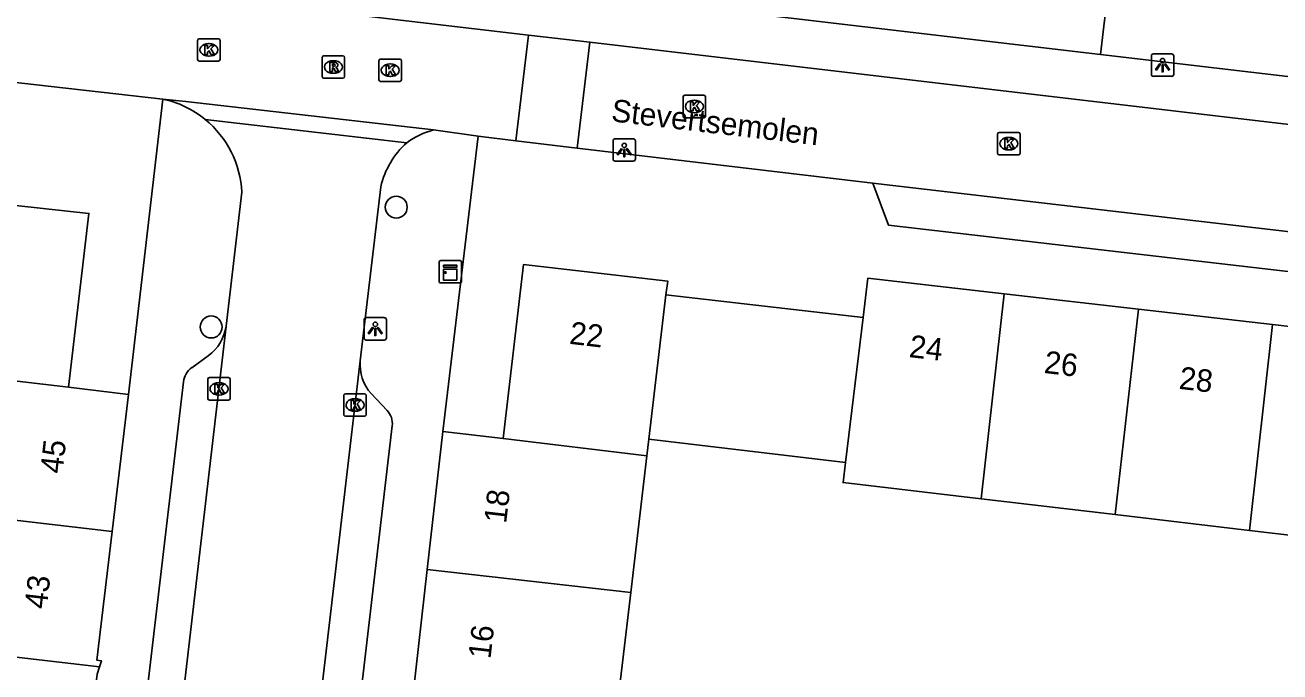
# Model space of a CAD drawing. Extents: x 161243 to 161752, y 384138 to 384885.
# Drawn here: x 161379.5 to 161435.4, y 384400.4 to 384429.2 of the extents above; entities that cross this region are included whole.
import ezdxf

# ---------------------------------------------------------------- set-up
doc = ezdxf.new("R2010")
doc.units = 0
for name, color, linetype in [('IMGEO_Boom', 7, 'Continuous'), ('IMGEO_Groenvoorziening', 7, 'Continuous'), ('IMGEO_Kast', 7, 'Continuous'), ('IMGEO_Kolk', 7, 'Continuous'), ('IMGEO_Lichtpunt', 7, 'Continuous'), ('IMGEO_Openbare_ruimte_label', 7, 'Continuous'), ('IMGEO_Pand', 7, 'Continuous'), ('IMGEO_Pand_nummerreeks', 7, 'Continuous'), ('IMGEO_Parkeervlak_open', 7, 'Continuous'), ('IMGEO_Rijbaan_lokaal_open', 7, 'Continuous'), ('IMGEO_Rioolput', 7, 'Continuous'), ('IMGEO_Voetpad_open', 7, 'Continuous')]:
    doc.layers.add(name, color=color, linetype=linetype)

msp = doc.modelspace()

# ---------------------------------------------------------------- linework, layer by layer
at = {"layer": 'IMGEO_Boom'}
for centre in [(161396.026, 384421.095), (161387.773, 384415.756)]:
    msp.add_circle(centre, 0.489, dxfattribs=at)
at = {"layer": 'IMGEO_Groenvoorziening'}
msp.add_lwpolyline([(161427.439, 384427.904), (161432.833, 384473.658)], dxfattribs=at)
at = {"layer": 'IMGEO_Kast'}
for p, q in [((161397.935, 384417.793), (161397.935, 384418.634)), ((161397.935, 384418.634), (161397.935, 384417.793)), ((161398.01, 384418.718), (161398.851, 384418.718)), ((161398.851, 384418.718), (161398.01, 384418.718)), ((161398.935, 384418.643), (161398.935, 384417.802)), ((161398.935, 384417.802), (161398.935, 384418.643)), ((161398.86, 384417.718), (161398.019, 384417.718)), ((161398.019, 384417.718), (161398.86, 384417.718))]:
    msp.add_line(p, q, dxfattribs=at)
for points in [[(161398.13, 384418.508), (161398.73, 384418.508), (161398.73, 384418.423), (161398.13, 384418.423), (161398.13, 384418.508)], [(161398.13, 384418.333), (161398.73, 384418.333), (161398.73, 384417.844), (161398.13, 384417.844), (161398.13, 384418.333)]]:
    msp.add_lwpolyline(points, dxfattribs=at)
msp.add_circle((161398.214, 384418.182), 0.0377, dxfattribs=at)
for centre, start, end in [((161398.013, 384418.64), 92.4484, 184.2845), ((161398.013, 384418.64), 92.4484, 184.2845), ((161398.857, 384418.64), 2.4484, 94.2845), ((161398.857, 384418.64), 2.4484, 94.2845), ((161398.013, 384417.796), 182.4484, 274.2845), ((161398.013, 384417.796), 182.4484, 274.2845), ((161398.857, 384417.796), 272.4484, 4.2845), ((161398.857, 384417.796), 272.4484, 4.2845)]:
    msp.add_arc(centre, 0.0779, start, end, dxfattribs=at)
at = {"layer": 'IMGEO_Kolk'}
for p, q in [((161387.168, 384427.68), (161387.168, 384428.532)), ((161387.243, 384428.606), (161388.095, 384428.606)), ((161388.169, 384428.532), (161388.169, 384427.68)), ((161387.656, 384428.386), (161387.681, 384428.386)), ((161388.095, 384427.606), (161387.243, 384427.606)), ((161387.679, 384427.826), (161387.654, 384427.826)), ((161395.256, 384426.773), (161395.256, 384427.625)), ((161395.331, 384427.699), (161396.183, 384427.699)), ((161395.744, 384427.479), (161395.769, 384427.479)), ((161396.257, 384427.625), (161396.257, 384426.773)), ((161395.767, 384426.919), (161395.742, 384426.919)), ((161396.183, 384426.699), (161395.331, 384426.699)), ((161408.822, 384425.158), (161408.822, 384426.01)), ((161408.897, 384426.084), (161409.749, 384426.084)), ((161409.31, 384425.864), (161409.335, 384425.864)), ((161409.823, 384426.01), (161409.823, 384425.158)), ((161409.333, 384425.304), (161409.308, 384425.304)), ((161409.749, 384425.084), (161408.897, 384425.084)), ((161422.848, 384423.5), (161422.848, 384424.352)), ((161422.923, 384424.426), (161423.775, 384424.426)), ((161423.336, 384424.206), (161423.361, 384424.206)), ((161423.849, 384424.352), (161423.849, 384423.5)), ((161423.359, 384423.646), (161423.334, 384423.646)), ((161423.775, 384423.426), (161422.923, 384423.426)), ((161387.62, 384412.571), (161387.62, 384413.423)), ((161387.695, 384413.497), (161388.547, 384413.497)), ((161388.621, 384413.423), (161388.621, 384412.571)), ((161388.108, 384413.277), (161388.133, 384413.277)), ((161388.547, 384412.497), (161387.695, 384412.497)), ((161388.131, 384412.717), (161388.106, 384412.717)), ((161393.687, 384411.849), (161393.687, 384412.701)), ((161393.762, 384412.775), (161394.614, 384412.775)), ((161394.175, 384412.555), (161394.2, 384412.555)), ((161394.688, 384412.701), (161394.688, 384411.849)), ((161394.614, 384411.775), (161393.762, 384411.775)), ((161394.198, 384411.995), (161394.173, 384411.995))]:
    msp.add_line(p, q, dxfattribs=at)
for points in [[(161387.168, 384427.68), (161387.168, 384428.532)], [(161387.243, 384428.606), (161388.095, 384428.606)], [(161388.169, 384428.532), (161388.169, 384427.68)], [(161387.489, 384428.306), (161387.612, 384428.306), (161387.612, 384428.155), (161387.742, 384428.306), (161387.906, 384428.306), (161387.76, 384428.155), (161387.913, 384427.906), (161387.761, 384427.906), (161387.676, 384428.07), (161387.612, 384428.003), (161387.612, 384427.906), (161387.489, 384427.906), (161387.489, 384428.306)], [(161388.095, 384427.606), (161387.243, 384427.606)], [(161395.256, 384426.773), (161395.256, 384427.625)], [(161395.331, 384427.699), (161396.183, 384427.699)], [(161395.577, 384427.399), (161395.7, 384427.399), (161395.7, 384427.248), (161395.83, 384427.399), (161395.994, 384427.399), (161395.848, 384427.248), (161396.001, 384426.999), (161395.849, 384426.999), (161395.764, 384427.163), (161395.7, 384427.096), (161395.7, 384426.999), (161395.577, 384426.999), (161395.577, 384427.399)], [(161396.257, 384427.625), (161396.257, 384426.773)], [(161396.183, 384426.699), (161395.331, 384426.699)], [(161408.822, 384425.158), (161408.822, 384426.01)], [(161408.897, 384426.084), (161409.749, 384426.084)], [(161409.143, 384425.784), (161409.266, 384425.784), (161409.266, 384425.633), (161409.396, 384425.784), (161409.56, 384425.784), (161409.414, 384425.633), (161409.567, 384425.384), (161409.415, 384425.384), (161409.33, 384425.548), (161409.266, 384425.481), (161409.266, 384425.384), (161409.143, 384425.384), (161409.143, 384425.784)], [(161409.823, 384426.01), (161409.823, 384425.158)], [(161409.749, 384425.084), (161408.897, 384425.084)], [(161422.848, 384423.5), (161422.848, 384424.352)], [(161422.923, 384424.426), (161423.775, 384424.426)], [(161423.169, 384424.126), (161423.292, 384424.126), (161423.292, 384423.975), (161423.422, 384424.126), (161423.586, 384424.126), (161423.44, 384423.975), (161423.593, 384423.726), (161423.441, 384423.726), (161423.356, 384423.89), (161423.292, 384423.823), (161423.292, 384423.726), (161423.169, 384423.726), (161423.169, 384424.126)], [(161423.849, 384424.352), (161423.849, 384423.5)], [(161423.775, 384423.426), (161422.923, 384423.426)], [(161387.62, 384412.571), (161387.62, 384413.423)], [(161387.695, 384413.497), (161388.547, 384413.497)], [(161388.621, 384413.423), (161388.621, 384412.571)], [(161387.941, 384413.197), (161388.064, 384413.197), (161388.064, 384413.046), (161388.194, 384413.197), (161388.358, 384413.197), (161388.212, 384413.046), (161388.365, 384412.797), (161388.213, 384412.797), (161388.128, 384412.961), (161388.064, 384412.894), (161388.064, 384412.797), (161387.941, 384412.797), (161387.941, 384413.197)], [(161388.547, 384412.497), (161387.695, 384412.497)], [(161393.687, 384411.849), (161393.687, 384412.701)], [(161393.762, 384412.775), (161394.614, 384412.775)], [(161394.008, 384412.475), (161394.131, 384412.475), (161394.131, 384412.324), (161394.261, 384412.475), (161394.425, 384412.475), (161394.279, 384412.324), (161394.432, 384412.075), (161394.28, 384412.075), (161394.195, 384412.239), (161394.131, 384412.172), (161394.131, 384412.075), (161394.008, 384412.075), (161394.008, 384412.475)], [(161394.688, 384412.701), (161394.688, 384411.849)], [(161394.614, 384411.775), (161393.762, 384411.775)]]:
    msp.add_lwpolyline(points, dxfattribs=at)
for centre, start, end in [((161387.245, 384428.53), 91.552, 178.448), ((161387.245, 384428.53), 91.552, 178.448), ((161388.093, 384428.53), 1.552, 88.448), ((161388.093, 384428.53), 1.552, 88.448), ((161387.245, 384427.682), 181.552, 268.448), ((161387.245, 384427.682), 181.552, 268.448), ((161388.093, 384427.682), 271.552, 358.448), ((161388.093, 384427.682), 271.552, 358.448), ((161395.333, 384427.623), 91.552, 178.448), ((161395.333, 384427.623), 91.552, 178.448), ((161396.181, 384427.623), 1.552, 88.448), ((161396.181, 384427.623), 1.552, 88.448), ((161395.333, 384426.775), 181.552, 268.448), ((161395.333, 384426.775), 181.552, 268.448), ((161396.181, 384426.775), 271.552, 358.448), ((161396.181, 384426.775), 271.552, 358.448), ((161408.899, 384426.008), 91.552, 178.448), ((161408.899, 384426.008), 91.552, 178.448), ((161409.747, 384426.008), 1.552, 88.448), ((161409.747, 384426.008), 1.552, 88.448), ((161408.899, 384425.16), 181.552, 268.448), ((161408.899, 384425.16), 181.552, 268.448), ((161409.747, 384425.16), 271.552, 358.448), ((161409.747, 384425.16), 271.552, 358.448), ((161422.925, 384424.35), 91.552, 178.448), ((161422.925, 384424.35), 91.552, 178.448), ((161423.773, 384424.35), 1.552, 88.448), ((161423.773, 384424.35), 1.552, 88.448), ((161422.925, 384423.502), 181.552, 268.448), ((161422.925, 384423.502), 181.552, 268.448), ((161423.773, 384423.502), 271.552, 358.448), ((161423.773, 384423.502), 271.552, 358.448), ((161387.697, 384413.421), 91.552, 178.448), ((161387.697, 384413.421), 91.552, 178.448), ((161388.545, 384413.421), 1.552, 88.448), ((161388.545, 384413.421), 1.552, 88.448), ((161387.697, 384412.573), 181.552, 268.448), ((161387.697, 384412.573), 181.552, 268.448), ((161388.545, 384412.573), 271.552, 358.448), ((161388.545, 384412.573), 271.552, 358.448), ((161393.764, 384412.699), 91.552, 178.448), ((161393.764, 384412.699), 91.552, 178.448), ((161394.612, 384412.699), 1.552, 88.448), ((161394.612, 384412.699), 1.552, 88.448), ((161393.764, 384411.851), 181.552, 268.448), ((161393.764, 384411.851), 181.552, 268.448), ((161394.612, 384411.851), 271.552, 358.448), ((161394.612, 384411.851), 271.552, 358.448)]:
    msp.add_arc(centre, 0.0765, start, end, dxfattribs=at)
for centre, major_axis, ratio, start_param, end_param in [((161387.655, 384428.106), (-0.387, 0.002), 0.722429, 4.712389, 7.853982), ((161387.68, 384428.106), (-0.39, 0.002), 0.717154, 1.570796, 4.712389), ((161395.743, 384427.199), (-0.387, 0.002), 0.722429, 4.712389, 7.853982), ((161395.768, 384427.199), (-0.39, 0.002), 0.717154, 1.570796, 4.712389), ((161409.309, 384425.584), (-0.387, 0.002), 0.722429, 4.712389, 7.853982), ((161409.334, 384425.584), (-0.39, 0.002), 0.717154, 1.570796, 4.712389), ((161423.335, 384423.926), (-0.387, 0.002), 0.722429, 4.712389, 7.853982), ((161423.36, 384423.926), (-0.39, 0.002), 0.717154, 1.570796, 4.712389), ((161388.107, 384412.997), (-0.387, 0.002), 0.722429, 4.712389, 7.853982), ((161388.132, 384412.997), (-0.39, 0.002), 0.717154, 1.570796, 4.712389), ((161394.174, 384412.275), (-0.387, 0.002), 0.722429, 4.712389, 7.853982), ((161394.199, 384412.275), (-0.39, 0.002), 0.717154, 1.570796, 4.712389)]:
    msp.add_ellipse(centre, major_axis=major_axis, ratio=ratio, start_param=start_param, end_param=end_param, dxfattribs=at)
at = {"layer": 'IMGEO_Lichtpunt'}
for p, q in [((161429.706, 384427.829), (161429.706, 384427.022)), ((161429.706, 384427.829), (161429.706, 384427.022)), ((161430.608, 384427.924), (161429.8, 384427.924)), ((161430.608, 384427.924), (161429.8, 384427.924)), ((161430.702, 384427.022), (161430.702, 384427.829)), ((161430.702, 384427.022), (161430.702, 384427.829)), ((161429.8, 384426.928), (161430.608, 384426.928)), ((161429.8, 384426.928), (161430.608, 384426.928)), ((161405.696, 384424.05), (161405.696, 384423.243)), ((161405.696, 384424.05), (161405.696, 384423.243)), ((161406.598, 384424.145), (161405.79, 384424.145)), ((161406.598, 384424.145), (161405.79, 384424.145)), ((161406.692, 384423.243), (161406.692, 384424.05)), ((161406.692, 384423.243), (161406.692, 384424.05)), ((161405.79, 384423.149), (161406.598, 384423.149)), ((161405.79, 384423.149), (161406.598, 384423.149)), ((161394.592, 384416.075), (161394.592, 384415.268)), ((161394.592, 384416.075), (161394.592, 384415.268)), ((161395.494, 384416.17), (161394.686, 384416.17)), ((161395.494, 384416.17), (161394.686, 384416.17)), ((161395.588, 384415.268), (161395.588, 384416.075)), ((161395.588, 384415.268), (161395.588, 384416.075)), ((161394.686, 384415.174), (161395.494, 384415.174)), ((161394.686, 384415.174), (161395.494, 384415.174))]:
    msp.add_line(p, q, dxfattribs=at)
for points in [[(161430.08, 384427.493), (161430.119, 384427.465), (161429.931, 384427.203), (161429.893, 384427.23), (161430.08, 384427.493)], [(161430.182, 384427.445), (161430.229, 384427.445), (161430.229, 384427.123), (161430.182, 384427.123), (161430.182, 384427.445)], [(161430.292, 384427.465), (161430.33, 384427.492), (161430.517, 384427.23), (161430.478, 384427.202), (161430.292, 384427.465)], [(161406.07, 384423.714), (161406.109, 384423.686), (161405.921, 384423.424), (161405.883, 384423.451), (161406.07, 384423.714)], [(161406.172, 384423.666), (161406.219, 384423.666), (161406.219, 384423.344), (161406.172, 384423.344), (161406.172, 384423.666)], [(161406.282, 384423.686), (161406.32, 384423.713), (161406.507, 384423.451), (161406.468, 384423.423), (161406.282, 384423.686)], [(161394.966, 384415.739), (161395.005, 384415.711), (161394.817, 384415.449), (161394.779, 384415.476), (161394.966, 384415.739)], [(161395.068, 384415.691), (161395.115, 384415.691), (161395.115, 384415.369), (161395.068, 384415.369), (161395.068, 384415.691)], [(161395.178, 384415.711), (161395.216, 384415.738), (161395.403, 384415.476), (161395.364, 384415.448), (161395.178, 384415.711)]]:
    msp.add_lwpolyline(points, dxfattribs=at)
for centre in [(161430.205, 384427.627), (161406.195, 384423.848), (161395.091, 384415.873)]:
    msp.add_circle(centre, 0.0994, dxfattribs=at)
for centre, start, end in [((161429.8, 384427.829), 90, 180), ((161429.8, 384427.829), 90, 180), ((161430.608, 384427.829), 0, 90), ((161430.608, 384427.829), 0, 90), ((161429.8, 384427.022), 180, 270), ((161429.8, 384427.022), 180, 270), ((161430.608, 384427.022), 270, 0), ((161430.608, 384427.022), 270, 360), ((161405.79, 384424.05), 90, 180), ((161405.79, 384424.05), 90, 180), ((161406.598, 384424.05), 0, 90), ((161406.598, 384424.05), 0, 90), ((161405.79, 384423.243), 180, 270), ((161405.79, 384423.243), 180, 270), ((161406.598, 384423.243), 270, 0), ((161406.598, 384423.243), 270, 360), ((161394.686, 384416.075), 90, 180), ((161394.686, 384416.075), 90, 180), ((161395.494, 384416.075), 0, 90), ((161395.494, 384416.075), 0, 90), ((161394.686, 384415.268), 180, 270), ((161394.686, 384415.268), 180, 270), ((161395.494, 384415.268), 270, 0), ((161395.494, 384415.268), 270, 360)]:
    msp.add_arc(centre, 0.0946, start, end, dxfattribs=at)
at = {"layer": 'IMGEO_Pand'}
for points in [[(161376.061, 384421.492), (161382.318, 384420.819), (161381.408, 384413.065)], [(161400.801, 384410.777), (161401.706, 384418.545), (161408.14, 384417.794), (161408.057, 384417.189)], [(161416.852, 384416.18), (161417.063, 384417.929), (161423.139, 384417.232)], [(161408.057, 384417.189), (161407.286, 384410.751)], [(161408.057, 384417.189), (161416.852, 384416.18)], [(161422.108, 384408.094), (161423.139, 384417.232)], [(161423.139, 384417.232), (161429.127, 384416.546)], [(161429.127, 384416.546), (161428.094, 384407.392)], [(161429.127, 384416.546), (161435.115, 384415.86)], [(161416.852, 384416.18), (161416.056, 384409.721)], [(161434.08, 384406.689), (161435.115, 384415.86)], [(161435.115, 384415.86), (161441.102, 384415.173)], [(161381.408, 384413.065), (161375.166, 384413.798)], [(161381.408, 384413.065), (161384.082, 384412.738)], [(161384.082, 384412.738), (161383.357, 384406.631)], [(161398.105, 384411.096), (161397.406, 384404.939)], [(161398.105, 384411.096), (161400.801, 384410.777)], [(161407.2, 384410.016), (161400.801, 384410.777)], [(161407.286, 384410.751), (161407.2, 384410.016)], [(161416.056, 384409.721), (161407.286, 384410.751)], [(161407.2, 384410.016), (161406.484, 384403.913)], [(161422.108, 384408.094), (161415.958, 384408.816), (161416.056, 384409.721)], [(161428.094, 384407.392), (161422.108, 384408.094)], [(161374.421, 384407.672), (161383.357, 384406.631)], [(161434.08, 384406.689), (161428.094, 384407.392)], [(161440.066, 384405.987), (161434.08, 384406.689)], [(161383.357, 384406.631), (161382.676, 384400.9), (161382.874, 384400.88), (161382.786, 384400.607)], [(161397.406, 384404.939), (161396.761, 384399.263), (161396.639, 384399.27), (161396.607, 384398.945)], [(161406.484, 384403.913), (161397.406, 384404.939)], [(161406.484, 384403.913), (161405.779, 384397.909)], [(161382.786, 384400.607), (161373.691, 384401.666)], [(161382.786, 384400.607), (161382.68, 384400.278), (161382.051, 384394.962), (161382.312, 384394.905), (161382.283, 384394.576)]]:
    msp.add_lwpolyline(points, dxfattribs=at)
at = {"layer": 'IMGEO_Parkeervlak_open'}
msp.add_lwpolyline([(161459.347, 384417.271), (161457.727, 384415.687), (161417.974, 384420.297), (161417.282, 384422.167)], dxfattribs=at)
at = {"layer": 'IMGEO_Rijbaan_lokaal_open'}
for points in [[(161336.535, 384438.485), (161336.257, 384436.376), (161382.402, 384431.06), (161401.922, 384428.768)], [(161401.363, 384424.054), (161401.922, 384428.768)], [(161401.922, 384428.768), (161404.653, 384428.447)], [(161404.094, 384423.73), (161404.653, 384428.447)], [(161404.653, 384428.447), (161443.686, 384423.864), (161452.639, 384422.825)], [(161385.608, 384425.915), (161367.914, 384427.91)], [(161397.686, 384424.536), (161386.646, 384425.81), (161385.608, 384425.915)], [(161396.501, 384423.968), (161387.504, 384425.007)], [(161397.686, 384424.536), (161399.676, 384424.254)], [(161399.676, 384424.254), (161401.363, 384424.054)], [(161404.094, 384423.73), (161401.363, 384424.054)], [(161417.282, 384422.167), (161404.094, 384423.73)], [(161394.42, 384414.251), (161395.335, 384422.009)], [(161452.092, 384418.115), (161417.282, 384422.167)], [(161389.139, 384421.761), (161388.436, 384415.795)], [(161388.436, 384415.795), (161382.703, 384366.584)], [(161388.778, 384366.166), (161394.42, 384414.251)]]:
    msp.add_lwpolyline(points, dxfattribs=at)
for centre, radius, start, end in [((161384.678, 384421.539), 4.473, 50.8205, 77.9997), ((161384.679, 384421.549), 4.465, 2.7202, 50.7483), ((161398.643, 384421.019), 3.645, 105.2232, 125.9959), ((161399.039, 384421.131), 3.807, 131.8146, 166.6631)]:
    msp.add_arc(centre, radius, start, end, dxfattribs=at)
at = {"layer": 'IMGEO_Rioolput'}
for p, q in [((161392.723, 384426.919), (161392.723, 384427.771)), ((161392.798, 384427.845), (161393.65, 384427.845)), ((161393.211, 384427.625), (161393.236, 384427.625)), ((161393.724, 384427.771), (161393.724, 384426.919)), ((161393.65, 384426.845), (161392.798, 384426.845)), ((161393.234, 384427.065), (161393.209, 384427.065))]:
    msp.add_line(p, q, dxfattribs=at)
for points in [[(161392.723, 384426.919), (161392.723, 384427.771)], [(161392.798, 384427.845), (161393.65, 384427.845)], [(161393.312, 384427.543), (161393.06, 384427.545), (161393.06, 384427.145)], [(161393.238, 384427.464), (161393.184, 384427.464), (161393.184, 384427.383)], [(161393.724, 384427.771), (161393.724, 384426.919)], [(161393.65, 384426.845), (161392.798, 384426.845)], [(161393.06, 384427.145), (161393.184, 384427.145), (161393.184, 384427.307), (161393.195, 384427.307)], [(161393.184, 384427.383), (161393.236, 384427.383)], [(161393.242, 384427.278), (161393.313, 384427.145), (161393.453, 384427.145), (161393.388, 384427.271)]]:
    msp.add_lwpolyline(points, dxfattribs=at)
for centre, radius, start, end in [((161392.8, 384427.769), 0.0765, 91.552, 178.448), ((161392.8, 384427.769), 0.0765, 91.552, 178.448), ((161393.244, 384427.368), 0.0964, 77.0061, 93.1865), ((161393.258, 384427.425), 0.0378, 276.6634, 79.6772), ((161393.311, 384427.433), 0.109, 350.3612, 89.416), ((161393.309, 384427.433), 0.112, 277.5842, 350.9817), ((161393.648, 384427.769), 0.0765, 1.552, 88.448), ((161393.648, 384427.769), 0.0765, 1.552, 88.448), ((161392.8, 384426.921), 0.0765, 181.552, 268.448), ((161392.8, 384426.921), 0.0765, 181.552, 268.448), ((161393.194, 384427.254), 0.0533, 26.0293, 88.6989), ((161393.22, 384427.572), 0.19, 274.7715, 282.9687), ((161393.293, 384427.218), 0.108, 29.5134, 73.7905), ((161393.648, 384426.921), 0.0765, 271.552, 358.448), ((161393.648, 384426.921), 0.0765, 271.552, 358.448)]:
    msp.add_arc(centre, radius, start, end, dxfattribs=at)
for centre, major_axis, ratio, start_param, end_param in [((161393.21, 384427.345), (-0.387, 0.002), 0.722429, 4.712389, 7.853982), ((161393.235, 384427.345), (-0.39, 0.002), 0.717154, 1.570796, 4.712389)]:
    msp.add_ellipse(centre, major_axis=major_axis, ratio=ratio, start_param=start_param, end_param=end_param, dxfattribs=at)
at = {"layer": 'IMGEO_Voetpad_open'}
for points in [[(161410.092, 384429.939), (161427.439, 384427.904)], [(161440.852, 384426.331), (161427.439, 384427.904)], [(161384.082, 384412.738), (161385.608, 384425.915)], [(161399.676, 384424.254), (161398.105, 384411.096)], [(161386.903, 384413.941), (161387.639, 384414.474)], [(161381.37, 384369.393), (161386.534, 384413.313)], [(161395.619, 384412.033), (161394.905, 384412.788)], [(161390.818, 384368.412), (161395.846, 384411.348)]]:
    msp.add_lwpolyline(points, dxfattribs=at)
for centre, radius, start, end in [((161386.485, 384416.071), 1.971, 305.8502, 351.942), ((161396.33, 384414.072), 1.918, 174.6559, 222.0259), ((161387.427, 384413.211), 0.899, 125.6584, 173.4663), ((161394.995, 384411.446), 0.857, 353.426, 43.243)]:
    msp.add_arc(centre, radius, start, end, dxfattribs=at)

# ---------------------------------------------------------------- texts
at = {"layer": 'IMGEO_Openbare_ruimte_label'}
msp.add_text('Stevertsemolen', height=1, rotation=353.337, dxfattribs=at).set_placement((161405.583, 384424.925))
at = {"layer": 'IMGEO_Pand_nummerreeks'}
for s, rotation, p in [('22', 353.3424, (161403.719, 384415.008)), ('24', 353.3059, (161418.869, 384414.415)), ('26', 353.3059, (161424.887, 384413.708)), ('28', 353.3059, (161430.907, 384413.001)), ('45', 83.3755, (161381.133, 384409.189)), ('18', 83.3746, (161400.928, 384406.972)), ('43', 83.3755, (161380.432, 384403.152)), ('16', 83.3746, (161400.227, 384400.931))]:
    msp.add_text(s, height=1, rotation=rotation, dxfattribs=at).set_placement(p)

doc.saveas('drawing.dxf')
